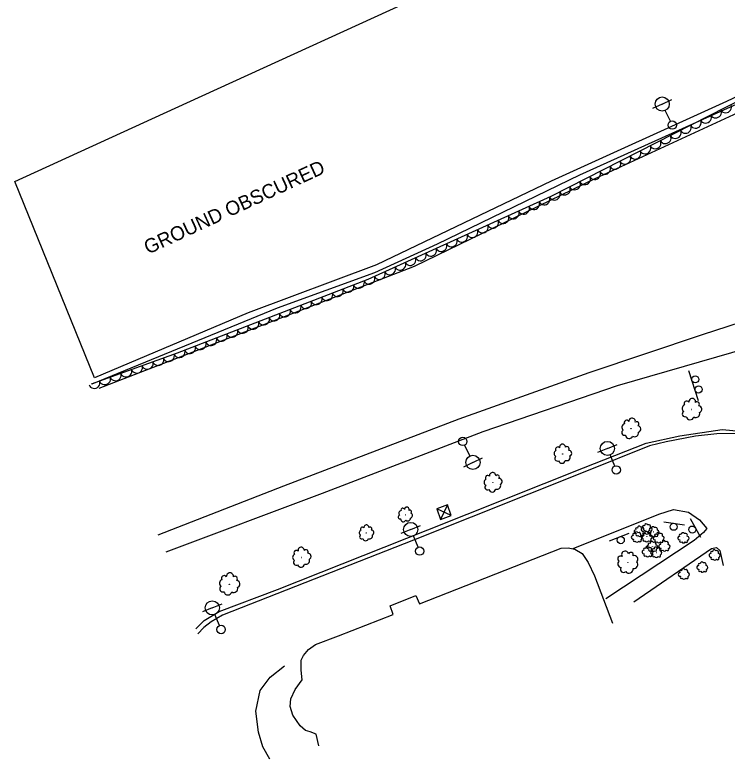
# Model space of a CAD drawing. Extents: x 1746719 to 1766531, y 631721 to 662391.
# Drawn here: x 1760787.4 to 1761039.3, y 638297.3 to 638560.4 of the extents above; entities that cross this region are included whole.
import ezdxf

# ---------------------------------------------------------------- set-up
doc = ezdxf.new("R2010")
doc.units = 0
for name, color, linetype in [('SURVEY - AERIAL SURVEY - Photo Control - Points - Elevations', 7, 'Continuous'), ('SURVEY - AERIAL SURVEY - Photo Control - Points - Locators', 7, 'Continuous'), ('SURVEY - AERIAL SURVEY - Photo Control with Text', 7, 'Continuous'), ('SURVEY - CENTERLINE - Existing Roads - Development', 7, 'Continuous'), ('SURVEY - CENTERLINE - Existing Roads Curve Text', 7, 'Continuous'), ('SURVEY - CONTROL - Grid', 7, 'Continuous'), ('SURVEY - CONTROL - Grid Text', 7, 'Continuous')]:
    doc.layers.add(name, color=color, linetype=linetype)

msp = doc.modelspace()

# ---------------------------------------------------------------- linework, layer by layer
at = {"layer": 'SURVEY - AERIAL SURVEY - Photo Control - Points - Elevations'}
for points in [[(1761413.23, 638926.74), (1761408, 638909.85), (1761400.43, 638888.84), (1761389.03, 638860.31), (1761376.42, 638831.76), (1761359.09, 638792.92), (1761344.73, 638761.96), (1761332.71, 638739.36), (1761314.65, 638710.12), (1761299.79, 638688.98), (1761278.73, 638661.82), (1761257, 638637.44), (1761245.56, 638626.69), (1761232.92, 638616.1), (1761213.76, 638603.68), (1761192.08, 638592.5), (1761171.03, 638582.9), (1761146.08, 638571.33), (1761101.8, 638551.52), (1761053.85, 638530.72), (1760992.48, 638502.41), (1760928.61, 638471.51), (1760891.46, 638457.14), (1760817.11, 638428.33)], [(1761116.87, 638560.97), (1761077.55, 638544.15), (1761040.33, 638527.79), (1760987.11, 638503.71), (1760936.77, 638479.32), (1760914.63, 638469.28), (1760880.11, 638456.76), (1760814.64, 638429.85)], [(1760838.09, 638376.57), (1760882.54, 638393.87), (1760944.48, 638417.56), (1760990.48, 638434.03), (1761030.62, 638447.48), (1761076.35, 638462.22), (1761118.08, 638475.73), (1761157.4, 638488.22), (1761199.46, 638501.14), (1761227.71, 638508.08), (1761255.89, 638513.13), (1761290.98, 638517.44), (1761321.62, 638518.68), (1761351.88, 638518.1), (1761374.91, 638515.69), (1761399.12, 638510.8), (1761420.3, 638505.12), (1761469.25, 638488.5)], [(1761186.4, 638491.04), (1761125.57, 638467.48), (1761064.6, 638447.77), (1761000.44, 638429.22), (1760952.84, 638412.98), (1760896.04, 638391.25), (1760840.82, 638370.42)], [(1760984.89, 638371.79), (1761015.09, 638383.88), (1761020.29, 638385.6), (1761025.65, 638384.58), (1761029.57, 638381.92), (1761032.11, 638378.86), (1761030.95, 638377.41), (1761027.61, 638374.64), (1760996.45, 638353.99)], [(1761006.26, 638352.91), (1761033.8, 638371.74), (1761035.56, 638372.14), (1761036.75, 638371.09), (1761037.93, 638365.73)], [(1760877.55, 638297.29), (1760875.12, 638301.62), (1760873.5, 638306.79), (1760872.63, 638314.27), (1760874.18, 638321.56), (1760877.69, 638326.22), (1760882.7, 638330.3)]]:
    msp.add_lwpolyline(points, dxfattribs=at)
at = {"layer": 'SURVEY - AERIAL SURVEY - Photo Control - Points - Locators'}
msp.add_lwpolyline([(1761138.11, 638574.27), (1761083.37, 638550.69), (1761039.1, 638529.86), (1760977.05, 638501.62), (1760915.34, 638472.04), (1760869.94, 638455.03), (1760815.49, 638432.05), (1760787.37, 638501.52), (1760848.15, 638529.34), (1760941.72, 638572.08)], dxfattribs=at)
at = {"layer": 'SURVEY - AERIAL SURVEY - Photo Control with Text'}
msp.add_lwpolyline([(1761141.29, 638574.46), (1761051.51, 638534.15), (1760976.94, 638496.17), (1760912.21, 638466.91), (1760844.74, 638440.8), (1760814.3, 638429.85)], dxfattribs=at)
for centre, radius in [((1761026.75, 638420.91), 0.042), ((1761005.31, 638414.11), 0.0406), ((1760981.13, 638405.18), 0.0375), ((1760956.45, 638395.07), 0.0383), ((1760925.49, 638383.67), 0.0297), ((1761010.91, 638378.59), 0.022), ((1760911.68, 638377.21), 0.0312), ((1761007.45, 638375.77), 0.022), ((1761008.45, 638377.79), 0.022), ((1761010.89, 638375.93), 0.022), ((1761013.32, 638377.62), 0.022), ((1761015.15, 638375.53), 0.022), ((1761023.9, 638375.5), 0.022), ((1761017.18, 638372.6), 0.022), ((1761011.23, 638370.58), 0.022), ((1761012.88, 638372.39), 0.022), ((1761014.28, 638370.36), 0.022), ((1760888.8, 638368.57), 0.0391), ((1761034.95, 638369.41), 0.022), ((1761004.19, 638366.87), 0.0444), ((1761030.59, 638365.14), 0.022), ((1761024.07, 638362.7), 0.022), ((1760863.23, 638359.1), 0.0436)]:
    msp.add_circle(centre, radius, dxfattribs=at)
for centre, radius, start, end in [((1761025, 638422.98), 0.914, 34.2785, 211.5976), ((1761026.96, 638423.6), 1.2, 351.6598, 185.0795), ((1761028.68, 638422.8), 0.826, 311.6391, 130.3848), ((1761024.66, 638421.28), 1.3, 109.5655, 236.4112), ((1761024.44, 638419.33), 1.01, 119.7245, 294.7247), ((1761029.15, 638420.98), 1.2, 289.523, 86.3119), ((1761005.69, 638416.7), 1.16, 347.6464, 181.0661), ((1761026.21, 638418.64), 1.36, 189.4716, 345.31), ((1761028.24, 638419.46), 1.37, 238.5757, 16.1), ((1761003.32, 638414.61), 1.25, 105.5521, 232.3978), ((1761003.77, 638416.23), 0.884, 30.2651, 207.5842), ((1761007.3, 638415.8), 0.799, 307.6257, 126.3714), ((1761007.63, 638414.02), 1.16, 285.5096, 82.2985), ((1761002.98, 638412.75), 0.972, 115.7111, 290.7113), ((1761006.65, 638412.62), 1.33, 234.5623, 12.0866), ((1761004.63, 638411.96), 1.32, 185.4582, 341.2966), ((1760979.4, 638406.86), 0.816, 39.9608, 217.28), ((1760981.08, 638407.59), 1.07, 357.3422, 190.7619), ((1760982.68, 638407.03), 0.738, 317.3215, 136.0671), ((1760979.24, 638405.32), 1.16, 115.2479, 242.0936), ((1760979.22, 638403.57), 0.897, 125.4068, 300.4071), ((1760982.58, 638404.03), 1.22, 244.2581, 21.7823), ((1760983.26, 638405.45), 1.07, 295.2053, 91.9943), ((1760980.85, 638403.11), 1.22, 195.1539, 350.9924), ((1760954.64, 638396.76), 0.835, 41.308, 218.6272), ((1760956.34, 638397.54), 1.1, 358.6894, 192.1091), ((1760957.99, 638397), 0.754, 318.6687, 137.4143), ((1760958.62, 638395.41), 1.1, 296.5525, 93.3414), ((1760954.52, 638395.18), 1.18, 116.5951, 243.4407), ((1760954.54, 638393.38), 0.918, 126.754, 301.7543), ((1760957.96, 638393.93), 1.25, 245.6053, 23.1295), ((1760956.21, 638392.96), 1.24, 196.5011, 352.3396), ((1760924.58, 638385.36), 0.647, 22.674, 199.9932), ((1760926.02, 638385.51), 0.851, 340.0554, 173.4751), ((1760923.67, 638382.9), 0.712, 108.12, 283.1203), ((1760924.1, 638384.23), 0.917, 97.9611, 224.8068), ((1760927.1, 638384.71), 0.585, 300.0347, 118.7803), ((1760927.17, 638383.38), 0.852, 277.9185, 74.7074), ((1760924.79, 638382.18), 0.965, 177.8671, 333.7056), ((1760926.32, 638382.46), 0.971, 226.9713, 4.4955), ((1760910.12, 638377.37), 0.961, 113.8158, 240.6615), ((1760910.28, 638378.64), 0.678, 38.5288, 215.8479), ((1760911.69, 638379.21), 0.891, 355.9101, 189.3298), ((1760913.01, 638378.71), 0.613, 315.8894, 134.6351), ((1760913.46, 638377.39), 0.893, 293.7733, 90.5622), ((1761007.04, 638377.7), 0.629, 89.7719, 283.1916), ((1761007.32, 638378.66), 0.433, 49.7512, 228.4969), ((1761008.23, 638379.04), 0.631, 27.6351, 184.424), ((1761009.09, 638378.67), 0.719, 336.6878, 114.212), ((1761009.49, 638378.49), 0.629, 89.7719, 283.1916), ((1761009.78, 638379.45), 0.433, 49.7512, 228.4969), ((1761009.96, 638377.53), 0.479, 132.3906, 309.7097), ((1761009.66, 638377.68), 0.714, 287.5836, 83.4221), ((1761010.69, 638379.83), 0.631, 27.6351, 184.424), ((1761011.54, 638379.47), 0.719, 336.6878, 114.212), ((1761011.91, 638377.53), 0.629, 89.7719, 283.1916), ((1761012.2, 638378.48), 0.433, 49.7512, 228.4969), ((1761012.12, 638378.47), 0.714, 287.5836, 83.4221), ((1761013.11, 638378.86), 0.631, 27.6351, 184.424), ((1761013.96, 638378.5), 0.719, 336.6878, 114.212), ((1761014.54, 638377.51), 0.714, 287.5836, 83.4221), ((1760910.06, 638375.91), 0.746, 123.9747, 298.975), ((1760911.41, 638375.5), 1.01, 193.7218, 349.5603), ((1760912.87, 638376.22), 1.02, 242.826, 20.3502), ((1761006.04, 638375.68), 0.629, 89.7719, 283.1916), ((1761006.33, 638376.63), 0.433, 49.7512, 228.4969), ((1761007.24, 638377.01), 0.631, 27.6351, 184.424), ((1761007.5, 638376.74), 0.479, 132.3906, 309.7097), ((1761008.09, 638376.65), 0.719, 336.6878, 114.212), ((1761008.41, 638376.68), 0.679, 207.6776, 334.5233), ((1761008.67, 638375.66), 0.714, 287.5836, 83.4221), ((1761009.48, 638375.84), 0.629, 89.7719, 283.1916), ((1761009.44, 638376.71), 0.527, 217.8365, 32.8368), ((1761009.77, 638376.8), 0.433, 49.7512, 228.4969), ((1761010.68, 638377.18), 0.631, 27.6351, 184.424), ((1761010.87, 638377.47), 0.679, 207.6776, 334.5233), ((1761011.53, 638376.81), 0.719, 336.6878, 114.212), ((1761011.89, 638377.51), 0.527, 217.8365, 32.8368), ((1761012.37, 638376.56), 0.479, 132.3906, 309.7097), ((1761012.11, 638375.82), 0.714, 287.5836, 83.4221), ((1761013.28, 638376.51), 0.679, 207.6776, 334.5233), ((1761013.74, 638375.44), 0.629, 89.7719, 283.1916), ((1761014.03, 638376.39), 0.433, 49.7512, 228.4969), ((1761014.31, 638376.54), 0.527, 217.8365, 32.8368), ((1761014.93, 638376.77), 0.631, 27.6351, 184.424), ((1761015.79, 638376.41), 0.719, 336.6878, 114.212), ((1761016.37, 638375.42), 0.714, 287.5836, 83.4221), ((1761022.48, 638375.41), 0.629, 89.7719, 283.1916), ((1761022.77, 638376.37), 0.433, 49.7512, 228.4969), ((1761023.68, 638376.74), 0.631, 27.6351, 184.424), ((1761024.53, 638376.38), 0.719, 336.6878, 114.212), ((1761025.11, 638375.39), 0.714, 287.5836, 83.4221), ((1761006.51, 638374.71), 0.479, 132.3906, 309.7097), ((1761007.41, 638374.66), 0.679, 207.6776, 334.5233), ((1761008.44, 638374.69), 0.527, 217.8365, 32.8368), ((1761009.94, 638374.88), 0.479, 132.3906, 309.7097), ((1761010.85, 638374.82), 0.679, 207.6776, 334.5233), ((1761011.46, 638372.3), 0.629, 89.7719, 283.1916), ((1761011.75, 638373.25), 0.433, 49.7512, 228.4969), ((1761011.88, 638374.85), 0.527, 217.8365, 32.8368), ((1761012.66, 638373.63), 0.631, 27.6351, 184.424), ((1761013.51, 638373.27), 0.719, 336.6878, 114.212), ((1761014.2, 638374.47), 0.479, 132.3906, 309.7097), ((1761014.09, 638372.28), 0.714, 287.5836, 83.4221), ((1761015.11, 638374.42), 0.679, 207.6776, 334.5233), ((1761015.77, 638372.5), 0.629, 89.7719, 283.1916), ((1761016.06, 638373.46), 0.433, 49.7512, 228.4969), ((1761016.14, 638374.45), 0.527, 217.8365, 32.8368), ((1761016.97, 638373.84), 0.631, 27.6351, 184.424), ((1761017.82, 638373.48), 0.719, 336.6878, 114.212), ((1761018.4, 638372.48), 0.714, 287.5836, 83.4221), ((1761022.95, 638374.44), 0.479, 132.3906, 309.7097), ((1761023.86, 638374.39), 0.679, 207.6776, 334.5233), ((1761024.89, 638374.42), 0.527, 217.8365, 32.8368), ((1760886.92, 638370.25), 0.852, 42.3898, 219.7089), ((1760888.64, 638371.08), 1.12, 359.7711, 193.1908), ((1760890.33, 638370.57), 0.77, 319.7504, 138.4961), ((1760891.01, 638368.95), 1.12, 297.6343, 94.4232), ((1761003.24, 638369.57), 1.27, 15.3482, 208.7679), ((1761005.25, 638369.52), 0.874, 335.3275, 154.0731), ((1761009.82, 638370.49), 0.629, 89.7719, 283.1916), ((1761010.11, 638371.44), 0.433, 49.7512, 228.4969), ((1761011.01, 638371.82), 0.631, 27.6351, 184.424), ((1761011.93, 638371.33), 0.479, 132.3906, 309.7097), ((1761011.87, 638371.46), 0.719, 336.6878, 114.212), ((1761012.84, 638371.28), 0.679, 207.6776, 334.5233), ((1761012.87, 638370.27), 0.629, 89.7719, 283.1916), ((1761012.45, 638370.47), 0.714, 287.5836, 83.4221), ((1761013.16, 638371.22), 0.433, 49.7512, 228.4969), ((1761014.07, 638371.6), 0.631, 27.6351, 184.424), ((1761013.86, 638371.31), 0.527, 217.8365, 32.8368), ((1761014.92, 638371.24), 0.719, 336.6878, 114.212), ((1761015.5, 638370.25), 0.714, 287.5836, 83.4221), ((1761016.23, 638371.54), 0.479, 132.3906, 309.7097), ((1761017.14, 638371.48), 0.679, 207.6776, 334.5233), ((1761018.17, 638371.52), 0.527, 217.8365, 32.8368), ((1761033.83, 638370.27), 0.433, 49.7512, 228.4969), ((1761034.74, 638370.65), 0.631, 27.6351, 184.424), ((1761035.59, 638370.29), 0.719, 336.6878, 114.212), ((1761036.17, 638369.3), 0.714, 287.5836, 83.4221), ((1760886.83, 638368.64), 1.21, 117.6768, 244.5225), ((1760886.88, 638366.81), 0.936, 127.8357, 302.836), ((1760890.37, 638367.44), 1.28, 246.687, 24.2113), ((1761002, 638366.34), 1.37, 133.2539, 260.0996), ((1761001.61, 638368.14), 0.967, 57.9668, 235.286), ((1761006.48, 638367.96), 1.27, 313.2113, 110.0003), ((1761010.28, 638369.52), 0.479, 132.3906, 309.7097), ((1761011.19, 638369.47), 0.679, 207.6776, 334.5233), ((1761012.22, 638369.5), 0.527, 217.8365, 32.8368), ((1761013.34, 638369.3), 0.479, 132.3906, 309.7097), ((1761014.24, 638369.25), 0.679, 207.6776, 334.5233), ((1761015.27, 638369.28), 0.527, 217.8365, 32.8368), ((1761033.54, 638369.32), 0.629, 89.7719, 283.1916), ((1761034, 638368.35), 0.479, 132.3906, 309.7097), ((1761034.91, 638368.3), 0.679, 207.6776, 334.5233), ((1761035.94, 638368.33), 0.527, 217.8365, 32.8368), ((1760888.6, 638366.41), 1.27, 197.5828, 353.4213), ((1761002.62, 638364.36), 1.06, 143.4128, 318.4131), ((1761006.24, 638366.1), 1.45, 262.2641, 39.7883), ((1761029.18, 638365.05), 0.629, 89.7719, 283.1916), ((1761029.47, 638366), 0.433, 49.7512, 228.4969), ((1761030.38, 638366.38), 0.631, 27.6351, 184.424), ((1761031.23, 638366.02), 0.719, 336.6878, 114.212), ((1761031.81, 638365.03), 0.714, 287.5836, 83.4221), ((1760861.39, 638361.22), 0.949, 35.1003, 212.4194), ((1760863.41, 638361.9), 1.25, 352.4816, 185.9013), ((1761004.62, 638364.44), 1.44, 213.1599, 8.9984), ((1761022.65, 638362.61), 0.629, 89.7719, 283.1916), ((1761022.94, 638363.56), 0.433, 49.7512, 228.4969), ((1761023.85, 638363.94), 0.631, 27.6351, 184.424), ((1761024.7, 638363.58), 0.719, 336.6878, 114.212), ((1761025.28, 638362.59), 0.714, 287.5836, 83.4221), ((1761029.64, 638364.08), 0.479, 132.3906, 309.7097), ((1761030.55, 638364.03), 0.679, 207.6776, 334.5233), ((1761031.58, 638364.06), 0.527, 217.8365, 32.8368), ((1760861.06, 638359.45), 1.34, 110.3873, 237.233), ((1760865.21, 638361.09), 0.858, 312.4609, 131.2066), ((1760865.73, 638359.21), 1.25, 290.3448, 87.1337), ((1761023.12, 638361.64), 0.479, 132.3906, 309.7097), ((1761024.03, 638361.59), 0.679, 207.6776, 334.5233), ((1761025.06, 638361.62), 0.527, 217.8365, 32.8368), ((1760860.86, 638357.42), 1.04, 120.5462, 295.5465), ((1760864.8, 638357.62), 1.42, 239.3975, 16.9217), ((1760862.7, 638356.73), 1.41, 190.2933, 346.1318)]:
    msp.add_arc(centre, radius, start, end, dxfattribs=at)
for centre, major_axis in [((1761038.89, 638527.72), (-1.78, -0.91)), ((1761035.32, 638525.9), (-1.78, -0.91)), ((1761028.19, 638522.27), (-1.78, -0.91)), ((1761031.76, 638524.09), (-1.78, -0.91)), ((1761024.63, 638520.46), (-1.78, -0.91)), ((1761017.5, 638516.83), (-1.78, -0.91)), ((1761021.06, 638518.64), (-1.78, -0.91)), ((1761013.94, 638515.01), (-1.78, -0.91)), ((1761006.81, 638511.38), (-1.78, -0.91)), ((1761010.37, 638513.2), (-1.78, -0.91)), ((1761003.24, 638509.57), (-1.78, -0.91)), ((1760996.11, 638505.94), (-1.78, -0.91)), ((1760999.68, 638507.75), (-1.78, -0.91)), ((1760992.55, 638504.12), (-1.78, -0.91)), ((1760988.99, 638502.31), (-1.78, -0.91)), ((1760981.86, 638498.67), (-1.78, -0.91)), ((1760985.42, 638500.49), (-1.78, -0.91)), ((1760978.29, 638496.86), (-1.78, -0.91)), ((1760971.03, 638493.5), (-1.82, -0.82)), ((1760974.68, 638495.15), (-1.82, -0.82)), ((1760963.74, 638490.2), (-1.82, -0.82)), ((1760967.39, 638491.85), (-1.82, -0.82)), ((1760960.1, 638488.56), (-1.82, -0.82)), ((1760952.81, 638485.26), (-1.82, -0.82)), ((1760956.45, 638486.91), (-1.82, -0.82)), ((1760949.16, 638483.61), (-1.82, -0.82)), ((1760941.87, 638480.32), (-1.82, -0.82)), ((1760945.52, 638481.97), (-1.82, -0.82)), ((1760938.23, 638478.67), (-1.82, -0.82)), ((1760930.94, 638475.38), (-1.82, -0.82)), ((1760934.58, 638477.02), (-1.82, -0.82)), ((1760923.65, 638472.08), (-1.82, -0.82)), ((1760927.29, 638473.73), (-1.82, -0.82)), ((1760920, 638470.43), (-1.82, -0.82)), ((1760912.71, 638467.14), (-1.82, -0.82)), ((1760916.36, 638468.78), (-1.82, -0.82)), ((1760905.27, 638464.22), (-1.87, -0.72)), ((1760909, 638465.67), (-1.87, -0.72)), ((1760901.54, 638462.78), (-1.87, -0.72)), ((1760894.07, 638459.89), (-1.87, -0.72)), ((1760897.8, 638461.34), (-1.87, -0.72)), ((1760886.61, 638457), (-1.87, -0.72)), ((1760890.34, 638458.45), (-1.87, -0.72)), ((1760879.15, 638454.12), (-1.87, -0.72)), ((1760882.88, 638455.56), (-1.87, -0.72)), ((1760871.69, 638451.23), (-1.87, -0.72)), ((1760875.42, 638452.67), (-1.87, -0.72)), ((1760864.23, 638448.34), (-1.87, -0.72)), ((1760867.96, 638449.79), (-1.87, -0.72)), ((1760860.5, 638446.9), (-1.87, -0.72)), ((1760853.04, 638444.01), (-1.87, -0.72)), ((1760856.77, 638445.46), (-1.87, -0.72)), ((1760845.58, 638441.13), (-1.87, -0.72)), ((1760849.31, 638442.57), (-1.87, -0.72)), ((1760838.06, 638438.4), (-1.88, -0.68)), ((1760841.82, 638439.75), (-1.88, -0.68)), ((1760830.53, 638435.69), (-1.88, -0.68)), ((1760834.29, 638437.04), (-1.88, -0.68)), ((1760823, 638432.98), (-1.88, -0.68)), ((1760826.77, 638434.34), (-1.88, -0.68)), ((1760815.48, 638430.27), (-1.88, -0.68)), ((1760819.24, 638431.63), (-1.88, -0.68))]:
    msp.add_ellipse(centre, major_axis=major_axis, ratio=0.940188, start_param=0, end_param=3.141593, dxfattribs=at)
at = {"layer": 'SURVEY - CENTERLINE - Existing Roads - Development'}
for p, q in [((1761016.33, 638528.91), (1761019.71, 638530.54)), ((1761016.33, 638528.91), (1761012.95, 638527.28)), ((1761019.26, 638522.84), (1761017.41, 638526.66)), ((1760946.44, 638408.28), (1760948.3, 638404.46)), ((1760996.94, 638407.14), (1760993.48, 638405.71)), ((1760996.94, 638407.14), (1761000.41, 638408.58)), ((1760999.53, 638400.91), (1760997.9, 638404.83)), ((1760949.4, 638402.21), (1760946.02, 638400.57)), ((1760949.4, 638402.21), (1760952.77, 638403.85)), ((1760927.39, 638378.49), (1760923.93, 638377.05)), ((1760927.39, 638378.49), (1760930.86, 638379.92)), ((1760929.97, 638372.25), (1760928.35, 638376.18)), ((1760857.21, 638350.76), (1760860.69, 638352.17)), ((1760857.21, 638350.76), (1760853.74, 638349.36)), ((1760859.75, 638344.51), (1760858.15, 638348.45))]:
    msp.add_line(p, q, dxfattribs=at)
for centre, radius in [((1761016.33, 638528.91), 2.5), ((1761019.91, 638521.48), 1.5), ((1760945.79, 638409.63), 1.5), ((1760996.94, 638407.14), 2.5), ((1760949.4, 638402.21), 2.5), ((1761000.1, 638399.52), 1.5), ((1760927.39, 638378.49), 2.5), ((1760930.55, 638370.86), 1.5), ((1760857.21, 638350.76), 2.5), ((1760860.31, 638343.12), 1.5)]:
    msp.add_circle(centre, radius, dxfattribs=at)
at = {"layer": 'SURVEY - CENTERLINE - Existing Roads Curve Text'}
for points in [[(1760851.41, 638343.38), (1760854.31, 638346.27), (1760859.69, 638349.46), (1760880.27, 638357.23), (1760933.48, 638378.31), (1760988.53, 638400.23), (1761010.64, 638409.02), (1761022.55, 638411.63), (1761037.54, 638413.86), (1761043.9, 638413.26), (1761050.37, 638411.05), (1761054.93, 638408.02), (1761058.03, 638404.84), (1761057.64, 638403.48)], [(1761057.64, 638403.48), (1761053.72, 638407.08), (1761048.29, 638410.55), (1761042.95, 638412.4), (1761035.63, 638412.31), (1761028.12, 638411.42), (1761017.68, 638409.5), (1761011.84, 638408.05), (1760989.54, 638399.14), (1760928.39, 638374.74), (1760860.76, 638348.22), (1760856.75, 638345.81), (1760854.18, 638343.85), (1760852.03, 638341.53)], [(1760894.84, 638302.04), (1760894, 638306.16), (1760891.87, 638306.93), (1760890.17, 638307.36), (1760888.27, 638309.07), (1760885.71, 638312.77), (1760884.75, 638315.95), (1760884.98, 638318.6), (1760886.52, 638321.9), (1760888.96, 638325.28), (1760888.65, 638328.78), (1760888.65, 638332.28), (1760889.45, 638333.95), (1760891.21, 638336.02), (1760893.65, 638337.82), (1760901.84, 638340.89), (1760921.13, 638348.48), (1760920.17, 638351.5), (1760929.24, 638355.11), (1760930.52, 638352.2), (1760980.61, 638371.82), (1760983.04, 638372.05), (1760985.43, 638371.52), (1760988.03, 638369.94), (1760990.17, 638366.85), (1760992.34, 638362.04), (1760998.76, 638345.39)]]:
    msp.add_lwpolyline(points, dxfattribs=at)
at = {"layer": 'SURVEY - CONTROL - Grid'}
for p, q in [((1761029.23, 638423.98), (1761025.73, 638434.62)), ((1761016.86, 638381.24), (1761024.27, 638380.08)), ((1761026.19, 638382.35), (1761029.86, 638375.81)), ((1760997.72, 638374.48), (1761004.71, 638377.21))]:
    msp.add_line(p, q, dxfattribs=at)
for centre in [(1761028.02, 638431.55), (1761029.19, 638427.99), (1761020.39, 638379.45), (1761026.97, 638378.46), (1761001.68, 638374.71)]:
    msp.add_circle(centre, 1.25, dxfattribs=at)
at = {"layer": 'SURVEY - CONTROL - Grid Text'}
for p, q in [((1760941.71, 638383.42), (1760936.58, 638385.81)), ((1760940.34, 638387.18), (1760937.95, 638382.05)), ((1760939.15, 638384.61), (1760939.15, 638384.61))]:
    msp.add_line(p, q, dxfattribs=at)
msp.add_lwpolyline([(1760941.71, 638383.42), (1760940.34, 638387.18), (1760936.58, 638385.81), (1760937.95, 638382.05), (1760941.71, 638383.42)], dxfattribs=at)

# ---------------------------------------------------------------- texts
at = {"layer": 'SURVEY - AERIAL SURVEY - Photo Control - Points - Locators'}
msp.add_text('GROUND OBSCURED', height=5, rotation=24.7484, dxfattribs=at).set_placement((1760834.47, 638475.67))

doc.saveas('drawing.dxf')
